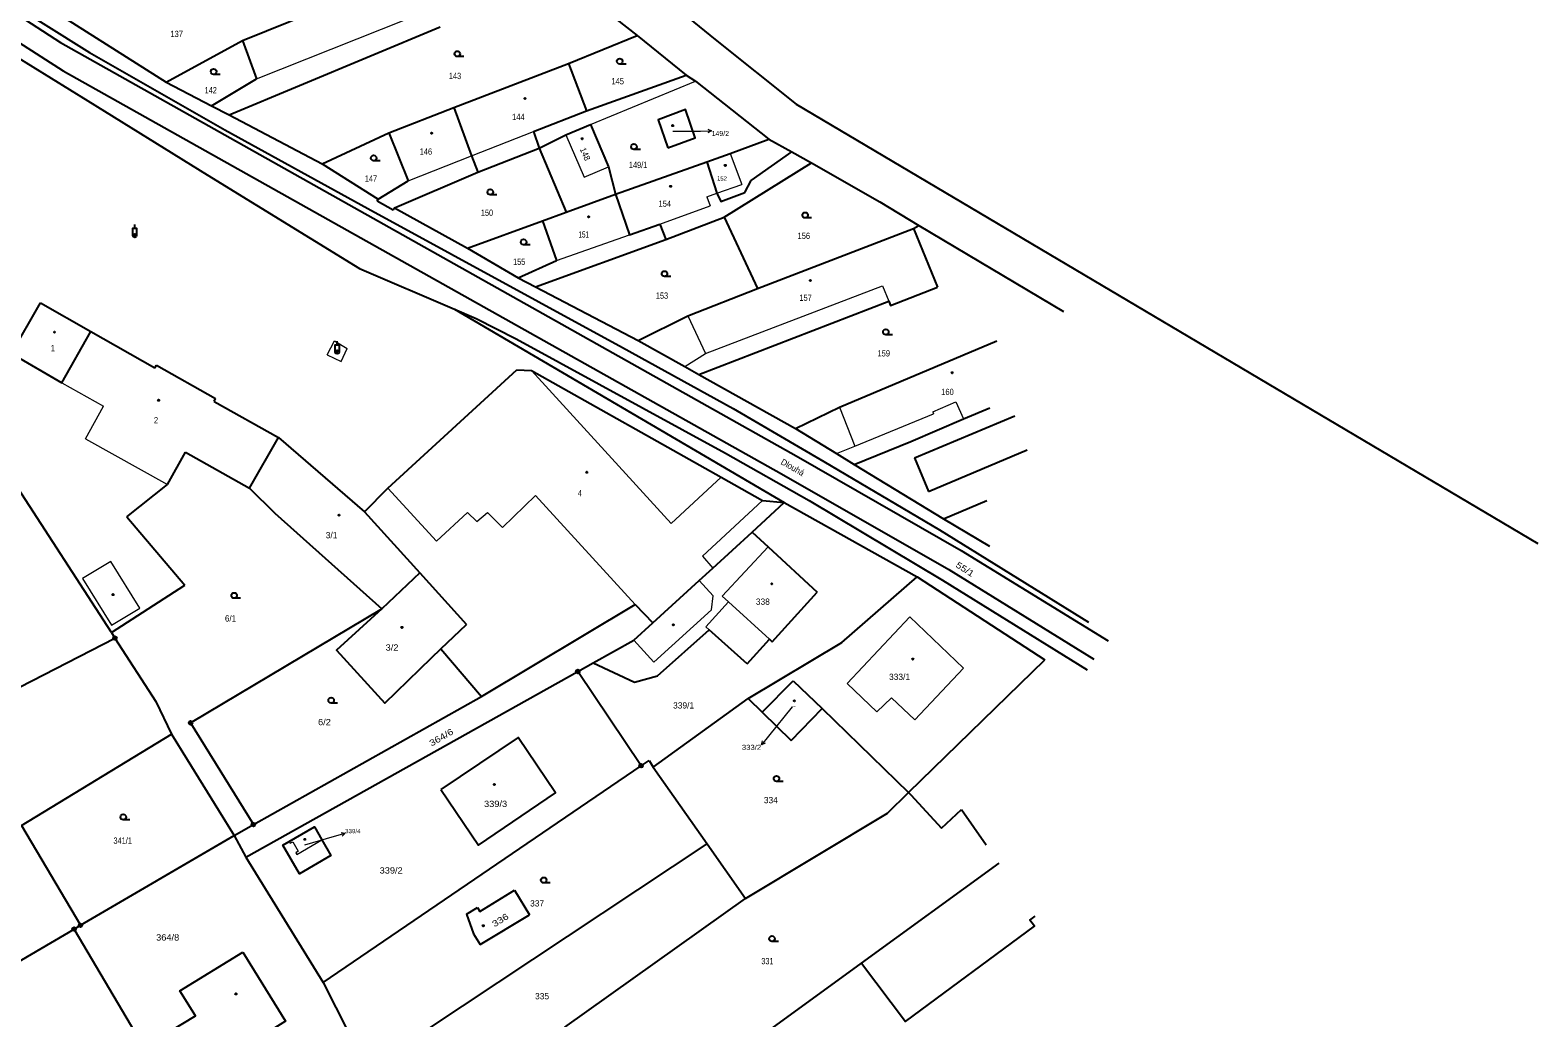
# Model space of a CAD drawing. Extents: x -592965 to -592390, y -1145071 to -1144631.
# Drawn here: x -592594.1 to -592390, y -1144927.6 to -1144793.9 of the extents above; entities that cross this region are included whole.
import ezdxf
from ezdxf.enums import TextEntityAlignment as Align

# ---------------------------------------------------------------- set-up
doc = ezdxf.new("R2010")
doc.units = 0
doc.header["$LTSCALE"] = 0.17
doc.layers.add('4', color=7, linetype='Continuous', lineweight=25)

msp = doc.modelspace()

# ---------------------------------------------------------------- linework, layer by layer
at = {"layer": '4'}
for p, q in [((-592593.65, -1144719.8), (-592501.36, -1144795.12)), ((-592627.84, -1144771.11), (-592589.96, -1144795.52)), ((-592630.17, -1144773.28), (-592589.61, -1144799.37)), ((-592613.84, -1144786.45), (-592586.25, -1144803.41)), ((-592524.07, -1144785.03), (-592511.92, -1144794.58)), ((-592598.96, -1144788.81), (-592586.05, -1144796.87)), ((-592565.34, -1144795.24), (-592552.56, -1144790.13)), ((-592589.18, -1144792.33), (-592575.67, -1144800.88)), ((-592567.15, -1144805.34), (-592538.58, -1144793.41)), ((-592521.18, -1144798.36), (-592511.92, -1144794.58)), ((-592511.92, -1144794.58), (-592505.25, -1144799.95)), ((-592589.96, -1144795.52), (-592490.39, -1144851.46)), ((-592575.67, -1144800.88), (-592565.34, -1144795.24)), ((-592565.34, -1144795.24), (-592563.45, -1144800.45)), ((-592501.36, -1144795.12), (-592490.36, -1144803.88)), ((-592586.05, -1144796.87), (-592567.7, -1144807.33)), ((-592536.7, -1144804.34), (-592521.18, -1144798.36)), ((-592535.365, -1144797.43), (-592536.24, -1144797.43)), ((-592521.18, -1144798.36), (-592518.76, -1144804.76)), ((-592513.385, -1144798.44), (-592514.26, -1144798.44)), ((-592589.61, -1144799.37), (-592492.36, -1144853.94)), ((-592569.54, -1144804.09), (-592563.45, -1144800.45)), ((-592568.365, -1144799.84), (-592569.24, -1144799.84)), ((-592575.67, -1144800.88), (-592569.54, -1144804.09)), ((-592586.25, -1144803.41), (-592570.12, -1144813.44)), ((-592569.54, -1144804.09), (-592567.15, -1144805.34)), ((-592545.53, -1144807.75), (-592536.7, -1144804.34)), ((-592536.7, -1144804.34), (-592534.32, -1144810.85)), ((-592490.36, -1144803.88), (-592389.97, -1144863.36)), ((-592567.15, -1144805.34), (-592554.54, -1144811.94)), ((-592567.7, -1144807.33), (-592548.35, -1144818)), ((-592554.54, -1144811.94), (-592545.53, -1144807.75)), ((-592545.53, -1144807.75), (-592542.88, -1144814.27)), ((-592525.92, -1144807.56), (-592525.18, -1144809.82)), ((-592494.07, -1144808.59), (-592490.96, -1144810.31)), ((-592534.32, -1144810.85), (-592533.48, -1144813.1)), ((-592533.48, -1144813.1), (-592525.18, -1144809.82)), ((-592525.18, -1144809.82), (-592521.51, -1144818.48)), ((-592511.465, -1144810.01), (-592512.34, -1144810.01)), ((-592496.47, -1144814.2), (-592490.96, -1144810.31)), ((-592490.96, -1144810.31), (-592488.31, -1144811.81)), ((-592554.54, -1144811.94), (-592546.94, -1144816.75)), ((-592546.695, -1144811.54), (-592547.57, -1144811.54)), ((-592502.48, -1144811.67), (-592501.1, -1144815.94)), ((-592500.13, -1144819.16), (-592488.31, -1144811.81)), ((-592488.31, -1144811.81), (-592479.03, -1144817.08)), ((-592570.12, -1144813.44), (-592549.48, -1144826.14)), ((-592544.77, -1144817.9), (-592533.48, -1144813.1)), ((-592497.31, -1144815.83), (-592496.47, -1144814.2)), ((-592547.1, -1144816.98), (-592544.92, -1144818.17)), ((-592530.915, -1144816.15), (-592531.79, -1144816.15)), ((-592521.51, -1144818.48), (-592514.83, -1144816.05)), ((-592514.83, -1144816.05), (-592512.95, -1144821.58)), ((-592479.03, -1144817.08), (-592473.78, -1144820.31)), ((-592548.35, -1144818), (-592513.89, -1144836.81)), ((-592524.73, -1144819.65), (-592521.51, -1144818.48)), ((-592500.13, -1144819.16), (-592495.61, -1144828.83)), ((-592579.92, -1144820.66), (-592579.92, -1144820.16)), ((-592534.85, -1144823.38), (-592524.73, -1144819.65)), ((-592524.73, -1144819.65), (-592522.82, -1144825.03)), ((-592512.95, -1144821.58), (-592508.84, -1144820.14)), ((-592495.61, -1144828.83), (-592474.49, -1144820.69)), ((-592488.285, -1144819.27), (-592489.16, -1144819.27)), ((-592474.49, -1144820.69), (-592473.78, -1144820.31)), ((-592474.49, -1144820.69), (-592471.26, -1144828.64)), ((-592473.78, -1144820.31), (-592454.2, -1144831.92)), ((-592526.395, -1144822.91), (-592527.27, -1144822.91)), ((-592525.64, -1144828.61), (-592508.01, -1144822.18)), ((-592534.85, -1144823.38), (-592528, -1144827.38)), ((-592528, -1144827.38), (-592522.82, -1144825.03)), ((-592549.48, -1144826.14), (-592536.63, -1144831.64)), ((-592507.325, -1144827.21), (-592508.2, -1144827.21)), ((-592528, -1144827.38), (-592525.64, -1144828.61)), ((-592525.64, -1144828.61), (-592511.77, -1144835.86)), ((-592505.06, -1144832.53), (-592495.61, -1144828.83)), ((-592596.58, -1144837.65), (-592592.65, -1144830.79)), ((-592592.65, -1144830.79), (-592585.87, -1144834.65)), ((-592503.57, -1144840.45), (-592477.85, -1144830.53)), ((-592536.63, -1144831.64), (-592492.02, -1144857.82)), ((-592536.63, -1144831.64), (-592533.69, -1144832.9)), ((-592533.69, -1144832.9), (-592528.29, -1144835.66)), ((-592511.77, -1144835.86), (-592505.06, -1144832.53)), ((-592589.79, -1144841.58), (-592585.87, -1144834.65)), ((-592585.87, -1144834.65), (-592577.21, -1144839.58)), ((-592477.355, -1144835.1), (-592478.23, -1144835.1)), ((-592552.51, -1144836.44), (-592552.51, -1144835.94)), ((-592528.29, -1144835.66), (-592499.94, -1144851.11)), ((-592513.89, -1144836.81), (-592498.9, -1144845.09)), ((-592511.77, -1144835.86), (-592505.43, -1144839.41)), ((-592484.5, -1144844.88), (-592463.2, -1144835.91)), ((-592596.58, -1144837.65), (-592589.79, -1144841.58)), ((-592577.21, -1144839.58), (-592576.98, -1144839.19)), ((-592576.98, -1144839.19), (-592568.97, -1144843.71)), ((-592505.43, -1144839.41), (-592503.57, -1144840.45)), ((-592545.65, -1144855.86), (-592528.18, -1144839.85)), ((-592528.18, -1144839.85), (-592526.22, -1144839.91)), ((-592526.22, -1144839.91), (-592500.51, -1144854.35)), ((-592503.57, -1144840.45), (-592490.47, -1144847.79)), ((-592569.15, -1144844.14), (-592568.97, -1144843.71)), ((-592569.15, -1144844.14), (-592560.44, -1144849.01)), ((-592498.9, -1144845.09), (-592486.64, -1144852.23)), ((-592490.47, -1144847.79), (-592484.5, -1144844.88)), ((-592467.72, -1144846.48), (-592464.14, -1144844.97)), ((-592474.85, -1144849.53), (-592467.72, -1144846.48)), ((-592474.37, -1144851.75), (-592460.75, -1144846.08)), ((-592564.37, -1144855.86), (-592560.44, -1144849.01)), ((-592560.44, -1144849.01), (-592548.83, -1144859.05)), ((-592490.47, -1144847.79), (-592484.93, -1144851.18)), ((-592482.51, -1144852.66), (-592474.85, -1144849.53)), ((-592575.49, -1144855.38), (-592573.03, -1144850.99)), ((-592573.03, -1144850.99), (-592564.37, -1144855.86)), ((-592499.94, -1144851.11), (-592488.62, -1144857.55)), ((-592490.39, -1144851.46), (-592468.03, -1144864.29)), ((-592484.93, -1144851.18), (-592482.51, -1144852.66)), ((-592474.37, -1144851.75), (-592472.44, -1144856.31)), ((-592472.44, -1144856.31), (-592459.1, -1144850.65)), ((-592486.64, -1144852.23), (-592470.99, -1144861.52)), ((-592482.51, -1144852.66), (-592470.45, -1144859.99)), ((-592583.07, -1144875.42), (-592596.3, -1144855.01)), ((-592580.99, -1144859.75), (-592575.49, -1144855.38)), ((-592564.37, -1144855.86), (-592560.93, -1144859.26)), ((-592548.83, -1144859.05), (-592545.65, -1144855.86)), ((-592500.51, -1144854.35), (-592494.92, -1144857.54)), ((-592492.36, -1144853.94), (-592469.7, -1144866.88)), ((-592496.35, -1144861.81), (-592492.02, -1144857.82)), ((-592494.92, -1144857.54), (-592492.02, -1144857.82)), ((-592492.02, -1144857.82), (-592473.99, -1144867.87)), ((-592488.62, -1144857.55), (-592470.55, -1144868.31)), ((-592470.45, -1144859.99), (-592464.58, -1144857.51)), ((-592580.99, -1144859.75), (-592573.14, -1144868.99)), ((-592560.93, -1144859.26), (-592546.46, -1144872.2)), ((-592548.83, -1144859.05), (-592541.33, -1144867.33)), ((-592470.45, -1144859.99), (-592464.18, -1144863.71)), ((-592501.64, -1144866.69), (-592496.35, -1144861.81)), ((-592470.99, -1144861.52), (-592450.81, -1144874)), ((-592468.03, -1144864.29), (-592448.16, -1144876.52)), ((-592541.33, -1144867.33), (-592546.46, -1144872.2)), ((-592541.33, -1144867.33), (-592534.98, -1144874.33)), ((-592503.49, -1144868.37), (-592501.64, -1144866.69)), ((-592484.21, -1144876.76), (-592473.99, -1144867.87)), ((-592473.99, -1144867.87), (-592456.69, -1144879.08)), ((-592469.7, -1144866.88), (-592450.06, -1144879.01)), ((-592583.07, -1144875.42), (-592573.14, -1144868.99)), ((-592509.79, -1144874.09), (-592503.49, -1144868.37)), ((-592493.61, -1144876.65), (-592487.55, -1144869.95)), ((-592470.55, -1144868.31), (-592450.97, -1144880.44)), ((-592572.36, -1144887.63), (-592546.46, -1144872.2)), ((-592565.575, -1144870.77), (-592566.45, -1144870.77)), ((-592532.99, -1144884.08), (-592512.18, -1144871.61)), ((-592512.18, -1144871.61), (-592509.79, -1144874.09)), ((-592512.34, -1144876.44), (-592509.79, -1144874.09)), ((-592618.69, -1144894.73), (-592582.6, -1144876.15)), ((-592538.46, -1144877.61), (-592534.98, -1144874.33)), ((-592509.15, -1144881.25), (-592502.14, -1144875.03)), ((-592497.02, -1144879.66), (-592502.14, -1144875.03)), ((-592539.74, -1144878.83), (-592538.46, -1144877.61)), ((-592538.46, -1144877.61), (-592532.99, -1144884.08)), ((-592517.84, -1144879.51), (-592512.34, -1144876.44)), ((-592475.15, -1144897.07), (-592456.69, -1144879.08)), ((-592511.36, -1144893.44), (-592519.93, -1144880.68)), ((-592494.96, -1144886.19), (-592490.79, -1144881.96)), ((-592490.79, -1144881.96), (-592486.84, -1144885.71)), ((-592563.84, -1144901.4), (-592532.99, -1144884.08)), ((-592496.85, -1144884.33), (-592494.96, -1144886.19)), ((-592577.07, -1144884.73), (-592574.92, -1144889.15)), ((-592552.445, -1144884.96), (-592553.32, -1144884.96)), ((-592494.96, -1144886.19), (-592491.07, -1144890.01)), ((-592491.07, -1144890.01), (-592486.84, -1144885.71)), ((-592486.84, -1144885.71), (-592475.15, -1144897.07)), ((-592572.36, -1144887.63), (-592563.84, -1144901.4)), ((-592574.92, -1144889.15), (-592566.46, -1144902.87)), ((-592509.73, -1144893.61), (-592502.43, -1144904)), ((-592492.155, -1144895.55), (-592493.03, -1144895.55)), ((-592477.99, -1144899.84), (-592475.15, -1144897.07)), ((-592475.15, -1144897.07), (-592474.87, -1144897.37)), ((-592474.87, -1144897.37), (-592470.69, -1144901.88)), ((-592580.595, -1144900.76), (-592581.47, -1144900.76)), ((-592497.22, -1144911.4), (-592477.99, -1144899.84)), ((-592470.69, -1144901.88), (-592467.99, -1144899.38)), ((-592467.99, -1144899.38), (-592464.65, -1144904.13)), ((-592595.26, -1144901.52), (-592587.26, -1144915.04)), ((-592566.46, -1144902.87), (-592563.84, -1144901.4)), ((-592548.47, -1144934.53), (-592502.43, -1144904)), ((-592502.43, -1144904), (-592497.22, -1144911.4)), ((-592481.52, -1144920.17), (-592462.9, -1144906.64)), ((-592533.2, -1144913.15), (-592528.52, -1144910.27)), ((-592528.52, -1144910.27), (-592526.47, -1144913.6)), ((-592523.675, -1144909.31), (-592524.55, -1144909.31)), ((-592535.01, -1144913.53), (-592533.53, -1144912.62)), ((-592533.53, -1144912.62), (-592533.2, -1144913.15)), ((-592521.69, -1144928.84), (-592497.22, -1144911.4)), ((-592535.01, -1144913.53), (-592534.05, -1144916.18)), ((-592533.13, -1144917.66), (-592526.47, -1144913.6)), ((-592534.05, -1144916.18), (-592533.13, -1144917.66)), ((-592492.775, -1144917.23), (-592493.65, -1144917.23))]:
    msp.add_line(p, q, dxfattribs=at)
at = {"layer": '4', "lineweight": 13}
for p, q in [((-592563.45, -1144800.45), (-592539.69, -1144791.03)), ((-592518.2, -1144806.64), (-592504, -1144800.77)), ((-592534.32, -1144810.85), (-592525.92, -1144807.56)), ((-592542.88, -1144814.27), (-592534.32, -1144810.85)), ((-592499.31, -1144810.55), (-592497.72, -1144814.74)), ((-592501.1, -1144815.94), (-592497.72, -1144814.74)), ((-592502.45, -1144816.42), (-592501.1, -1144815.94)), ((-592502.45, -1144816.42), (-592502.01, -1144817.65)), ((-592508.84, -1144820.14), (-592502.01, -1144817.65)), ((-592522.82, -1144825.03), (-592512.95, -1144821.58)), ((-592502.67, -1144837.65), (-592478.7, -1144828.47)), ((-592478.7, -1144828.47), (-592477.85, -1144830.53)), ((-592505.06, -1144832.53), (-592502.67, -1144837.65)), ((-592553.87, -1144837.81), (-592552.87, -1144835.9)), ((-592552.87, -1144835.9), (-592551.15, -1144836.96)), ((-592551.97, -1144838.71), (-592551.15, -1144836.96)), ((-592553.87, -1144837.81), (-592551.97, -1144838.71)), ((-592505.43, -1144839.41), (-592502.67, -1144837.65)), ((-592589.79, -1144841.58), (-592584.14, -1144844.74)), ((-592526.22, -1144839.91), (-592507.31, -1144860.66)), ((-592586.58, -1144849.16), (-592584.14, -1144844.74)), ((-592484.5, -1144844.88), (-592482.42, -1144850.17)), ((-592471.89, -1144845.52), (-592471.77, -1144845.8)), ((-592482.42, -1144850.17), (-592471.77, -1144845.8)), ((-592586.58, -1144849.16), (-592575.49, -1144855.38)), ((-592484.93, -1144851.18), (-592482.42, -1144850.17)), ((-592545.65, -1144855.86), (-592539.08, -1144863.03)), ((-592507.31, -1144860.66), (-592500.51, -1144854.35)), ((-592530.15, -1144861.19), (-592525.68, -1144856.87)), ((-592525.68, -1144856.87), (-592512.18, -1144871.61)), ((-592503.07, -1144865.05), (-592494.92, -1144857.54)), ((-592533.62, -1144860.35), (-592532.15, -1144859.16)), ((-592532.15, -1144859.16), (-592530.15, -1144861.19)), ((-592500.4, -1144870.48), (-592494.18, -1144863.82)), ((-592503.07, -1144865.05), (-592501.64, -1144866.69)), ((-592503.49, -1144868.37), (-592501.62, -1144870.45)), ((-592502.6, -1144874.61), (-592499.55, -1144871.25)), ((-592501.84, -1144872.33), (-592501.62, -1144870.45)), ((-592483.45, -1144882.31), (-592474.98, -1144873.26)), ((-592474.98, -1144873.26), (-592467.7, -1144880.23)), ((-592502.6, -1144874.61), (-592502.14, -1144875.03)), ((-592474.33, -1144887.2), (-592467.7, -1144880.23)), ((-592483.45, -1144882.31), (-592479.44, -1144886.16)), ((-592479.44, -1144886.16), (-592477.47, -1144884.23)), ((-592477.47, -1144884.23), (-592474.33, -1144887.2))]:
    msp.add_line(p, q, dxfattribs=at)
at = {"layer": '4'}
for points in [[(-592525.92, -1144807.56), (-592518.76, -1144804.76), (-592505.25, -1144799.95)], [(-592505.25, -1144799.95), (-592504, -1144800.77), (-592494.07, -1144808.59)], [(-592525.18, -1144809.82), (-592521.57, -1144808.04), (-592518.2, -1144806.64)], [(-592518.2, -1144806.64), (-592515.78, -1144812.36), (-592514.83, -1144816.05)], [(-592514.83, -1144816.05), (-592502.48, -1144811.67), (-592499.31, -1144810.55), (-592494.07, -1144808.59)], [(-592547.1, -1144816.98), (-592546.94, -1144816.75), (-592542.88, -1144814.27)], [(-592501.1, -1144815.94), (-592500.58, -1144817.06), (-592497.31, -1144815.83)], [(-592544.92, -1144818.17), (-592544.77, -1144817.9), (-592534.85, -1144823.38)], [(-592508.84, -1144820.14), (-592508.01, -1144822.18), (-592500.13, -1144819.16)], [(-592580.17, -1144821.66), (-592580.17, -1144820.66), (-592579.67, -1144820.66), (-592579.67, -1144821.66)], [(-592477.85, -1144830.53), (-592477.61, -1144831.13), (-592471.26, -1144828.64)], [(-592552.76, -1144837.44), (-592552.76, -1144836.44), (-592552.26, -1144836.44), (-592552.26, -1144837.44)], [(-592496.35, -1144861.81), (-592494.18, -1144863.82), (-592487.55, -1144869.95)], [(-592546.46, -1144872.2), (-592552.59, -1144877.78), (-592546.04, -1144884.98), (-592539.74, -1144878.83)], [(-592583.07, -1144875.42), (-592582.6, -1144876.15), (-592577.07, -1144884.73)], [(-592497.02, -1144879.66), (-592493.98, -1144876.31), (-592493.61, -1144876.65)], [(-592510.29, -1144892.71), (-592509.73, -1144893.61), (-592496.85, -1144884.33), (-592484.21, -1144876.76)], [(-592564.89, -1144905.8), (-592519.93, -1144880.68), (-592517.84, -1144879.51)], [(-592517.84, -1144879.51), (-592512.28, -1144882.14), (-592509.15, -1144881.25)], [(-592616.08, -1144914.18), (-592595.26, -1144901.52), (-592574.92, -1144889.15)], [(-592554.39, -1144922.78), (-592511.36, -1144893.44), (-592510.29, -1144892.71)], [(-592588.13, -1144915.55), (-592587.26, -1144915.04), (-592566.46, -1144902.87)], [(-592566.46, -1144902.87), (-592564.89, -1144905.8), (-592554.39, -1144922.78)], [(-592512.18, -1144942.45), (-592481.52, -1144920.17), (-592475.56, -1144928.06), (-592458.12, -1144915.16), (-592458.74, -1144914.34), (-592458, -1144913.8)], [(-592610.8, -1144923.69), (-592608.64, -1144927.55), (-592588.13, -1144915.55)], [(-592570.16, -1144945.99), (-592570.98, -1144944.6), (-592588.13, -1144915.55)], [(-592554.39, -1144922.78), (-592550.98, -1144929.55), (-592548.47, -1144934.53)]]:
    msp.add_lwpolyline(points, dxfattribs=at)
for points in [[(-592507.75, -1144809.77), (-592504.05, -1144808.45), (-592505.34, -1144804.61), (-592509.05, -1144805.99)], [(-592538.46, -1144896.65), (-592533.38, -1144904.17), (-592522.95, -1144897.12), (-592528.02, -1144889.6)], [(-592554.59, -1144903.48), (-592553.38, -1144905.6), (-592557.62, -1144908.05), (-592559.85, -1144904.2), (-592558.99, -1144903.7), (-592555.6, -1144901.72)], [(-592565.26, -1144918.66), (-592559.51, -1144928.03), (-592562.38, -1144929.81), (-592561.72, -1144930.89), (-592564.47, -1144932.57), (-592565.11, -1144931.52), (-592568.04, -1144933.29), (-592568.3, -1144932.86), (-592571.92, -1144935.08), (-592575.33, -1144929.51), (-592571.71, -1144927.3), (-592573.79, -1144923.9)]]:
    msp.add_lwpolyline(points, close=True, dxfattribs=at)
at = {"layer": '4', "lineweight": 13}
for points in [[(-592521.57, -1144808.04), (-592519.09, -1144813.76), (-592515.78, -1144812.36)], [(-592507.06, -1144807.55), (-592503.315, -1144807.514), (-592501.815, -1144807.5)], [(-592502.317, -1144807.254), (-592501.815, -1144807.5), (-592502.313, -1144807.754)], [(-592471.89, -1144845.52), (-592468.78, -1144844.18), (-592467.72, -1144846.48)], [(-592539.08, -1144863.03), (-592534.85, -1144859.14), (-592533.62, -1144860.35)], [(-592500.4, -1144870.48), (-592499.55, -1144871.25), (-592493.98, -1144876.31)], [(-592512.34, -1144876.44), (-592509.66, -1144879.4), (-592501.84, -1144872.33)], [(-592490.9, -1144885.47), (-592494.124, -1144889.436), (-592495.07, -1144890.6)], [(-592494.561, -1144890.37), (-592495.07, -1144890.6), (-592494.949, -1144890.054)], [(-592556.88, -1144904.14), (-592552.882, -1144902.986), (-592551.441, -1144902.57)], [(-592551.991, -1144902.468), (-592551.441, -1144902.57), (-592551.852, -1144902.949)], [(-592558.99, -1144903.7), (-592558.86, -1144903.92), (-592558.52, -1144903.72), (-592557.77, -1144905.02), (-592558.12, -1144905.22), (-592557.99, -1144905.45), (-592554.59, -1144903.48)]]:
    msp.add_lwpolyline(points, dxfattribs=at)
msp.add_lwpolyline([(-592579.24, -1144872.1), (-592583.15, -1144865.79), (-592586.99, -1144868.1), (-592583.07, -1144874.42)], close=True, dxfattribs=at)
at = {"layer": '4'}
for centre, radius in [((-592536.24, -1144797.055), 0.375), ((-592514.26, -1144798.065), 0.375), ((-592569.24, -1144799.465), 0.375), ((-592527.08, -1144803.11), 0.0875), ((-592507.09, -1144806.77), 0.0875), ((-592539.72, -1144807.8), 0.0875), ((-592519.35, -1144808.56), 0.0875), ((-592547.57, -1144811.165), 0.375), ((-592512.34, -1144809.635), 0.375), ((-592499.97, -1144812.16), 0.0875), ((-592507.37, -1144815), 0.0875), ((-592531.79, -1144815.775), 0.375), ((-592518.48, -1144819.13), 0.0875), ((-592489.16, -1144818.895), 0.375), ((-592579.92, -1144821.66), 0.25), ((-592579.92, -1144821.66), 0.025), ((-592527.27, -1144822.535), 0.375), ((-592508.2, -1144826.835), 0.375), ((-592488.44, -1144827.74), 0.0875), ((-592590.78, -1144834.74), 0.0875), ((-592478.23, -1144834.725), 0.375), ((-592552.51, -1144837.44), 0.25), ((-592552.51, -1144837.44), 0.025), ((-592469.26, -1144840.23), 0.0875), ((-592576.69, -1144843.96), 0.0875), ((-592518.71, -1144853.71), 0.0875), ((-592552.26, -1144859.52), 0.0875), ((-592582.85, -1144870.27), 0.0875), ((-592566.45, -1144870.395), 0.375), ((-592493.67, -1144868.81), 0.0875), ((-592507.01, -1144874.36), 0.0875), ((-592582.6, -1144876.15), 0.25), ((-592582.6, -1144876.15), 0.0164), ((-592543.74, -1144874.71), 0.0875), ((-592474.58, -1144878.99), 0.0875), ((-592519.93, -1144880.68), 0.25), ((-592519.93, -1144880.68), 0.0164), ((-592553.32, -1144884.585), 0.375), ((-592490.61, -1144884.65), 0.0875), ((-592572.36, -1144887.63), 0.25), ((-592572.36, -1144887.63), 0.0164), ((-592511.36, -1144893.44), 0.25), ((-592511.36, -1144893.44), 0.0164), ((-592531.24, -1144895.98), 0.0875), ((-592493.03, -1144895.175), 0.375), ((-592581.47, -1144900.385), 0.375), ((-592563.84, -1144901.4), 0.25), ((-592563.84, -1144901.4), 0.0164), ((-592556.89, -1144903.4), 0.0875), ((-592524.55, -1144908.935), 0.375), ((-592587.26, -1144915.04), 0.25), ((-592587.26, -1144915.04), 0.0164), ((-592532.74, -1144915.1), 0.0875), ((-592588.13, -1144915.55), 0.25), ((-592588.13, -1144915.55), 0.0164), ((-592493.65, -1144916.855), 0.375), ((-592566.22, -1144924.33), 0.0875)]:
    msp.add_circle(centre, radius, dxfattribs=at)

# ---------------------------------------------------------------- texts
for s, height, width, p in [('137', 0.85, 0.75, (-592575.09, -1144794.79)), ('143', 0.85, 0.8, (-592537.38, -1144800.48)), ('145', 0.85, 0.75, (-592515.39, -1144801.19)), ('142', 0.85, 0.8, (-592570.45, -1144802.41)), ('144', 0.85, 0.75, (-592528.83, -1144806.03)), ('149/2', 0.1, 1.1, (-592507.06, -1144807.55)), ('146', 0.85, 0.75, (-592541.35, -1144810.72)), ('149/1', 0.85, 0.85, (-592513.018, -1144812.53)), ('147', 0.85, 0.7, (-592548.76, -1144814.36)), ('154', 0.85, 0.75, (-592509.01, -1144817.77)), ('150', 0.85, 0.8, (-592533.05, -1144818.99)), ('151', 0.85, 0.6, (-592519.84, -1144821.93)), ('156', 0.85, 0.75, (-592490.19, -1144822.12)), ('155', 0.85, 0.8, (-592528.69, -1144825.63)), ('153', 0.85, 0.8, (-592509.36, -1144830.22)), ('157', 0.85, 0.75, (-592489.95, -1144830.5)), ('1', 0.85, 0.9, (-592591.29, -1144837.32)), ('159', 0.85, 0.75, (-592479.37, -1144838.03)), ('160', 0.85, 0.75, (-592470.74, -1144843.25)), ('2', 0.85, 0.9, (-592577.32, -1144847.08)), ('4', 0.85, 0.8, (-592519.92, -1144856.95)), ('6/1', 0.85, 0.95, (-592567.7, -1144873.92)), ('3/2', 0.85, 1.1, (-592545.95, -1144877.86)), ('333/2', 0.1, 1.3, (-592490.9, -1144885.47)), ('6/2', 0.85, 1.1, (-592555.1, -1144887.95)), ('333/2', 0.68, 1.15, (-592497.73, -1144891.28)), ('339/3', 0.85, 1.1, (-592532.63, -1144899.02)), ('339/4', 0.57, 1.1, (-592551.441, -1144902.57)), ('341/1', 0.85, 0.85, (-592582.796, -1144904)), ('339/4', 0.1, 1.25, (-592556.88, -1144904.14)), ('339/2', 0.85, 1.1, (-592546.764, -1144908.03)), ('364/8', 0.85, 1.1, (-592577.02, -1144917.1)), ('331', 0.85, 0.8, (-592495.09, -1144920.31))]:
    msp.add_text(s, height=height, dxfattribs=dict(at, width=width)).set_placement(p)
for s, height, p in [('149/2', 0.68, (-592501.815, -1144808.18)), ('3/1', 0.85, (-592554.06, -1144862.64)), ('338', 0.85, (-592495.83, -1144871.65)), ('333/1', 0.85, (-592477.8, -1144881.82)), ('339/1', 0.85, (-592507.038, -1144885.69)), ('334', 0.85, (-592494.75, -1144898.51)), ('337', 0.85, (-592526.39, -1144912.49)), ('335', 0.85, (-592525.72, -1144925.06))]:
    msp.add_text(s, height=height, dxfattribs=at).set_placement(p)
for s, height, rotation, width, p in [('148', 0.85, 293.435, 0.95, (-592519.68, -1144809.97)), ('152', 0.6, 357.749, 0.8, (-592501.1, -1144814.2)), ('55/1', 0.85, 327.331, 1.2, (-592468.86, -1144866.48)), ('364/6', 0.85, 30.078, 1.25, (-592539.74, -1144890.85)), ('336', 0.85, 31.643, 1.25, (-592531.21, -1144915.32))]:
    msp.add_text(s, height=height, rotation=rotation, dxfattribs=dict(at, width=width)).set_placement(p)
at = {"layer": '4', "width": 0.95}
msp.add_text('Dlouhá', height=0.85, rotation=330.2, dxfattribs=at).set_placement((-592491.0592, -1144853.4102), align=Align.CENTER)

doc.saveas('drawing.dxf')
